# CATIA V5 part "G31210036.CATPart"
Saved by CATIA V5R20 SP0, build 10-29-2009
Part number: G31210036
Revision: 8
Definition: design
Nomenclature: G31210036
Source: made
Description: NOT SPECIFIED
Bounding box of the stored display mesh (mm): x -5 to 36, y -8 to 8, z -8 to 8
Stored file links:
  C:\Users\Raffaele\Desktop\3D X SITO CF\BOLEX\23-BUSH REF 312\G31210036.CATPart

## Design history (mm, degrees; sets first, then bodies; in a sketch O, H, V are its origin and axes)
Body1 "MANIFOLD_SOLID_BREP #9695" (main body)
  Solid1: solid without history
Body2 "MANIFOLD_SOLID_BREP #9838"
  Solid2: solid without history
Body3 "MANIFOLD_SOLID_BREP #9981"
  Solid3: solid without history
Body4 "MANIFOLD_SOLID_BREP #10124"
  Solid4: solid without history
Body5 "MANIFOLD_SOLID_BREP #10267"
  Solid5: solid without history
Body6 "MANIFOLD_SOLID_BREP #10410"
  Solid6: solid without history
Body7 "MANIFOLD_SOLID_BREP #10553"
  Solid7: solid without history
Body8 "MANIFOLD_SOLID_BREP #10698"
  Solid8: solid without history
Body9 "MANIFOLD_SOLID_BREP #10843"
  Solid9: solid without history
Body10 "MANIFOLD_SOLID_BREP #10988"
  Solid10: solid without history
Body11 "MANIFOLD_SOLID_BREP #11133"
  Solid11: solid without history
Body12 "MANIFOLD_SOLID_BREP #11276"
  Solid12: solid without history
Body13 "MANIFOLD_SOLID_BREP #11419"
  Solid13: solid without history
Body14 "MANIFOLD_SOLID_BREP #11564"
  Solid14: solid without history
Body15 "MANIFOLD_SOLID_BREP #11709"
  Solid15: solid without history
Body16 "MANIFOLD_SOLID_BREP #11854"
  Solid16: solid without history
Body17 "MANIFOLD_SOLID_BREP #11999"
  Solid17: solid without history
Body18 "MANIFOLD_SOLID_BREP #12144"
  Solid18: solid without history
Body19 "MANIFOLD_SOLID_BREP #12289"
  Solid19: solid without history
Body20 "MANIFOLD_SOLID_BREP #12434"
  Solid20: solid without history
Body21 "MANIFOLD_SOLID_BREP #12579"
  Solid21: solid without history
Body22 "MANIFOLD_SOLID_BREP #12724"
  Solid22: solid without history
Body23 "MANIFOLD_SOLID_BREP #12869"
  Solid23: solid without history
Body24 "MANIFOLD_SOLID_BREP #13014"
  Solid24: solid without history
Body25 "MANIFOLD_SOLID_BREP #13159"
  Solid25: solid without history
Body26 "MANIFOLD_SOLID_BREP #13304"
  Solid26: solid without history
Body27 "MANIFOLD_SOLID_BREP #13449"
  Solid27: solid without history
Body28 "MANIFOLD_SOLID_BREP #13594"
  Solid28: solid without history
Body29 "MANIFOLD_SOLID_BREP #13737"
  Solid29: solid without history
Body30 "MANIFOLD_SOLID_BREP #13882"
  Solid30: solid without history
Body31 "MANIFOLD_SOLID_BREP #14027"
  Solid31: solid without history
Body32 "MANIFOLD_SOLID_BREP #14170"
  Solid32: solid without history
Body33 "MANIFOLD_SOLID_BREP #14315"
  Solid33: solid without history
Body34 "MANIFOLD_SOLID_BREP #14460"
  Solid34: solid without history
Body35 "MANIFOLD_SOLID_BREP #14603"
  Solid35: solid without history
Body36 "MANIFOLD_SOLID_BREP #14746"
  Solid36: solid without history
Body37 "MANIFOLD_SOLID_BREP #14891"
  Solid37: solid without history
Body38 "MANIFOLD_SOLID_BREP #15036"
  Solid38: solid without history
Body39 "MANIFOLD_SOLID_BREP #15181"
  Solid39: solid without history
Body40 "MANIFOLD_SOLID_BREP #15326"
  Solid40: solid without history
Body41 "MANIFOLD_SOLID_BREP #15471"
  Solid41: solid without history
Body42 "MANIFOLD_SOLID_BREP #15616"
  Solid42: solid without history
Body43 "MANIFOLD_SOLID_BREP #15761"
  Solid43: solid without history
Body44 "MANIFOLD_SOLID_BREP #15904"
  Solid44: solid without history
Body45 "MANIFOLD_SOLID_BREP #16049"
  Solid45: solid without history
Body46 "MANIFOLD_SOLID_BREP #16194"
  Solid46: solid without history
Body47 "MANIFOLD_SOLID_BREP #16337"
  Solid47: solid without history
Body48 "MANIFOLD_SOLID_BREP #16482"
  Solid48: solid without history
Body49 "MANIFOLD_SOLID_BREP #16627"
  Solid49: solid without history
Body50 "MANIFOLD_SOLID_BREP #16772"
  Solid50: solid without history
Body51 "MANIFOLD_SOLID_BREP #16917"
  Solid51: solid without history
Body52 "MANIFOLD_SOLID_BREP #17062"
  Solid52: solid without history
Body53 "MANIFOLD_SOLID_BREP #17207"
  Solid53: solid without history
Body54 "MANIFOLD_SOLID_BREP #17352"
  Solid54: solid without history
Body55 "MANIFOLD_SOLID_BREP #17497"
  Solid55: solid without history
Body56 "MANIFOLD_SOLID_BREP #17642"
  Solid56: solid without history
Body57 "MANIFOLD_SOLID_BREP #17785"
  Solid57: solid without history
Body58 "MANIFOLD_SOLID_BREP #17928"
  Solid58: solid without history
Body59 "MANIFOLD_SOLID_BREP #18071"
  Solid59: solid without history
Body60 "MANIFOLD_SOLID_BREP #18216"
  Solid60: solid without history
Body61 "MANIFOLD_SOLID_BREP #18361"
  Solid61: solid without history
Body62 "MANIFOLD_SOLID_BREP #18504"
  Solid62: solid without history
Body63 "MANIFOLD_SOLID_BREP #18649"
  Solid63: solid without history
Body64 "MANIFOLD_SOLID_BREP #18794"
  Solid64: solid without history
Body65 "MANIFOLD_SOLID_BREP #18937"
  Solid65: solid without history
Body66 "MANIFOLD_SOLID_BREP #19080"
  Solid66: solid without history
Body67 "MANIFOLD_SOLID_BREP #19225"
  Solid67: solid without history
Body68 "MANIFOLD_SOLID_BREP #19370"
  Solid68: solid without history
Body69 "MANIFOLD_SOLID_BREP #19515"
  Solid69: solid without history
Body70 "MANIFOLD_SOLID_BREP #19660"
  Solid70: solid without history
Body71 "MANIFOLD_SOLID_BREP #19805"
  Solid71: solid without history
Body72 "MANIFOLD_SOLID_BREP #19950"
  Solid72: solid without history
Body73 "MANIFOLD_SOLID_BREP #20095"
  Solid73: solid without history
